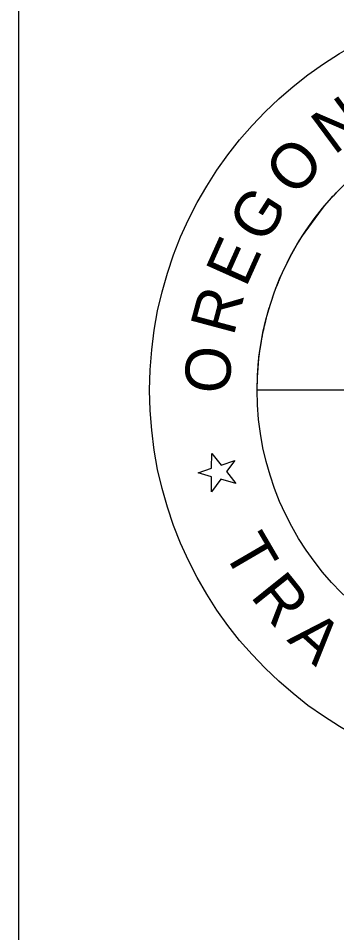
# Model space of a CAD drawing. Extents: x -1.2 to 17.3, y -1 to 2.5.
# Drawn here: x 0.0417 to 0.0821, y 1.8227 to 1.9389 of the extents above; entities that cross this region are included whole.
import ezdxf

# ---------------------------------------------------------------- set-up
doc = ezdxf.new("R2010")
doc.units = 0
doc.layers.add('P_ODOT_PLAN_Border', color=7, linetype='Continuous')
doc.layers.add('P_ODOT_PLAN_TBlock', color=7, linetype='Continuous')

msp = doc.modelspace()

# ---------------------------------------------------------------- linework, layer by layer
at = {"layer": 'P_ODOT_PLAN_Border'}
msp.add_lwpolyline([(0.04167, 0.04167), (16.625, 0.04167), (16.625, 1.95833), (0.04167, 1.95833)], close=True, dxfattribs=at)
msp.add_lwpolyline([(0.04167, 0.04167), (16.625, 0.04167), (16.625, 1.95833), (0.04167, 1.95833)], close=True, dxfattribs=at)
at = {"layer": 'P_ODOT_PLAN_TBlock'}
msp.add_lwpolyline([(0.08532, 1.89167), (0.07198, 1.89167), (0.07198, 1.89179), (0.07198, 1.89202), (0.072, 1.89291), (0.07201, 1.89333), (0.07208, 1.89447), (0.07219, 1.89563), (0.0722, 1.89585), (0.07236, 1.89696), (0.07238, 1.89705), (0.07238, 1.89705), (0.07238, 1.89706), (0.0724, 1.8972), (0.07242, 1.89735), (0.07247, 1.89764), (0.07251, 1.89785), (0.07256, 1.89818), (0.07263, 1.89851), (0.07271, 1.89893), (0.07281, 1.89939), (0.07291, 1.89985), (0.07306, 1.90047), (0.07315, 1.90084), (0.07329, 1.90135), (0.07342, 1.90181), (0.07351, 1.90211), (0.07351, 1.90211), (0.07351, 1.90212), (0.07353, 1.90217), (0.07366, 1.90259), (0.07386, 1.90322), (0.0741, 1.90392), (0.07436, 1.90462), (0.07455, 1.90511), (0.07467, 1.9054), (0.07469, 1.90545), (0.0747, 1.90549), (0.07472, 1.90552), (0.07472, 1.90553), (0.07472, 1.90553), (0.07473, 1.90555), (0.07476, 1.90561), (0.07481, 1.90574), (0.07508, 1.90636), (0.07522, 1.90668), (0.0753, 1.90686), (0.07535, 1.90697), (0.07553, 1.90735), (0.07577, 1.90783), (0.07609, 1.90848), (0.07639, 1.90904), (0.07656, 1.90935), (0.07662, 1.90945), (0.07691, 1.90995), (0.07701, 1.91013), (0.07713, 1.91033), (0.07729, 1.91059), (0.07743, 1.91083), (0.0776, 1.91109), (0.08025, 1.91476), (0.08043, 1.91497), (0.08058, 1.91516), (0.08093, 1.91557), (0.08103, 1.91568), (0.08122, 1.91589), (0.08128, 1.91596), (0.08159, 1.9163), (0.08173, 1.91645), (0.08177, 1.91649), (0.08201, 1.91674), (0.08235, 1.91709)], dxfattribs=at)
msp.add_lwpolyline([(0.06448, 1.88114), (0.0662, 1.88173), (0.06623, 1.8836), (0.0674, 1.88214), (0.06912, 1.88274), (0.06807, 1.88131), (0.06928, 1.8798), (0.06735, 1.88034), (0.06617, 1.87873), (0.06619, 1.88066)], close=True, dxfattribs=at)
for radius in [0.05, 0.03636]:
    msp.add_circle((0.10833, 1.89167), radius, dxfattribs=at)

# ---------------------------------------------------------------- texts
for s, rotation, p in [('N', 36.5188, (0.08171, 1.92146)), ('O', 47.0792, (0.07671, 1.91607)), ('G', 57.374, (0.07285, 1.91003)), ('E', 65.8562, (0.07053, 1.90459)), ('R', 75.0182, (0.06896, 1.89841)), ('O', 85.5786, (0.06839, 1.89108)), ('T', 300.2744, (0.06753, 1.87127)), ('R', 308.78, (0.071, 1.86546)), ('A', 317.942, (0.07565, 1.85985))]:
    msp.add_text(s, height=0.00574, rotation=rotation, dxfattribs=at).set_placement(p)

doc.saveas('drawing.dxf')
